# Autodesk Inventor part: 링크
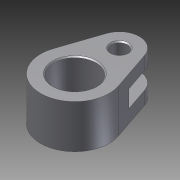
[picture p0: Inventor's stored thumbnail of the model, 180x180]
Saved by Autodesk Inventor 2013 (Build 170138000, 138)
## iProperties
Created: 2010-03
Part Number: 링크
Document SubType Name: Modeling
Designer: Administrator
Density: 1 g/cm^3
Material: 스테인리스강
Author: Administrator
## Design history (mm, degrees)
sketch "스케치1"
  geometry: L1 (-16.577, 44.609)-(-28.417, 9.615); L2 (16.577, 44.609)-(28.417, 9.615); C1 r 18.5 at (0, 0); C2 r 7 at (0, 39); A1 r 30 centre (0, 0) between (28.417, 9.615) and (-28.417, 9.615); A2 r 17.5 centre (0, 39) between (-16.577, 44.609) and (16.577, 44.609); 1 further point
  constraints: 4 centre point, 4 end point, 4 point on circle, 4 tangent, 3 coincident, 1 vertical alignment
  dimensions: "d0" = 37 diameter of C1; "d1" = 60 diameter of A1; "d2" = 35 diameter of A2; "d3" = 39 distance of A1.centre A2.centre; "d4" = 14 diameter of C2
extrude "돌출1" new body sketch "스케치1" distance "d5" = 38; taper "d6" = 0 deg
sketch "스케치2"
  geometry: L1 (32, 38)-(32, 0) reference; L2 (32, 0)-(18.5, 0) reference; L3 (18.5, 0)-(18.5, 38) reference; L4 (18.5, 38)-(32, 38) reference; L5 (-30, 0)-(-30, 38) reference; L6 (-30, 38)-(-18.5, 38) reference; L7 (-18.5, 38)-(-18.5, 0) reference; L8 (-18.5, 0)-(-30, 0) reference; L9 (56.5, 38)-(56.5, 0) reference; L10 (56.5, 0)-(46, 0) reference; L11 (46, 0)-(46, 38) reference; L12 (46, 38)-(56.5, 38) reference; L13 (79.593, 11.5)-(23.5, 11.5); L14 (23.5, 11.5)-(23.5, 26.5); L15 (23.5, 26.5)-(79.593, 26.5); L16 (79.593, 26.5)-(79.593, 11.5); 3 further points
  constraints: 8 end point, 2 midpoint, 2 parallel, 1 horizontal, 1 horizontal alignment, 1 perpendicular
  dimensions: "d7" = 33 distance between parallel lines of L14 L9; "d8" = 15 distance of L15.end L13.start
extrude "돌출2" cut sketch "스케치2" stored distance "d9" = 26; taper "d10" = 0 deg
chamfer "모따기1" distance "d11" = 1; stored, may be unused: second distance "d12" = 2, angle "d13" = 45 deg
node "솔리드1"
node "절단 모서리 투영1"
